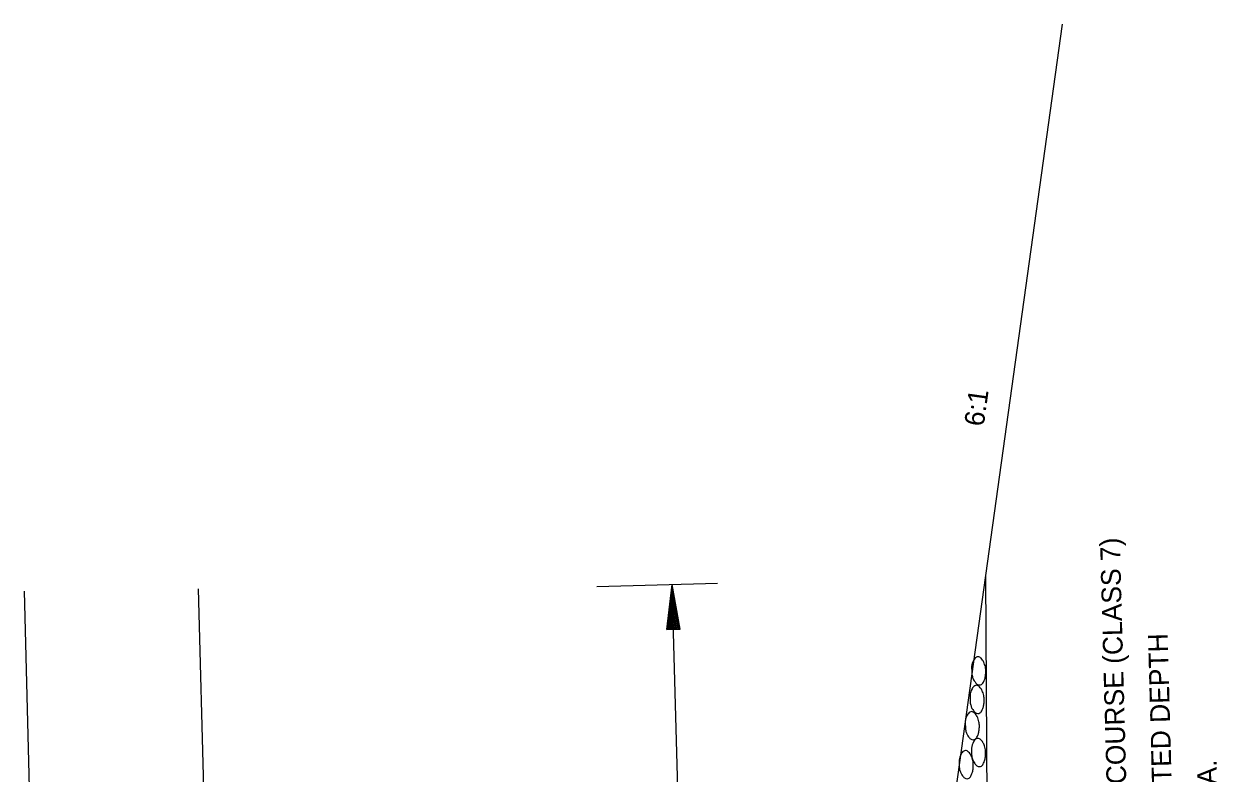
# Model space of a CAD drawing. Extents: x 1926836 to 1933254, y 596317 to 604524.
# Drawn here: x 1932418.2 to 1932782.8, y 597644.8 to 597872.5 of the extents above; entities that cross this region are included whole.
import ezdxf

# ---------------------------------------------------------------- set-up
doc = ezdxf.new("R2010")
doc.units = 0
doc.layers.add('Default', color=7, linetype='Continuous')

msp = doc.modelspace()

# ---------------------------------------------------------------- linework, layer by layer
at = {"layer": 'Default'}
for p, q in [((1932679.06, 597479.65), (1932733.75, 597872.49)), ((1932713.69, 597228.79), (1932710.43, 597704.89)), ((1932471.09, 597701.01), (1932477.06, 597478.58)), ((1932592.27, 597701.72), (1932628.91, 597702.7)), ((1932613.54, 597688.61), (1932615.21, 597702.34)), ((1932621.23, 597478.1), (1932615.21, 597702.34)), ((1932617.64, 597688.72), (1932615.21, 597702.34)), ((1932418.22, 597700.29), (1932424.29, 597474.09)), ((1932613.87, 597688.61), (1932615.27, 597700.05)), ((1932614.23, 597688.62), (1932615.34, 597697.68)), ((1932617.3, 597688.71), (1932615.27, 597700.05)), ((1932616.96, 597688.7), (1932615.34, 597697.68)), ((1932614.56, 597688.63), (1932615.4, 597695.39)), ((1932616.6, 597688.69), (1932615.4, 597695.39)), ((1932614.93, 597688.64), (1932615.46, 597693.08)), ((1932615.26, 597688.65), (1932615.52, 597690.79)), ((1932616.27, 597688.68), (1932615.46, 597693.08)), ((1932615.91, 597688.67), (1932615.52, 597690.79)), ((1932613.54, 597688.61), (1932617.64, 597688.72))]:
    msp.add_line(p, q, dxfattribs=at)
for points in [[(1932706.2, 597675.92), (1932706.17, 597677.44), (1932706.76, 597679.27), (1932707.6, 597680.22), (1932708.1, 597680.37), (1932709.04, 597679.9), (1932709.47, 597679.38), (1932709.98, 597678.42), (1932710.4, 597676.92), (1932710.46, 597676.19), (1932710.42, 597675.05), (1932710.23, 597673.84), (1932709.87, 597672.88), (1932709.19, 597671.97), (1932708.57, 597671.81), (1932707.79, 597672.05), (1932707.2, 597672.72), (1932706.75, 597673.36), (1932706.4, 597674.33), (1932706.24, 597674.96), (1932706.2, 597675.92)], [(1932705.72, 597667.26), (1932705.69, 597668.77), (1932706.28, 597670.61), (1932707.11, 597671.55), (1932707.61, 597671.7), (1932708.55, 597671.23), (1932708.98, 597670.71), (1932709.5, 597669.76), (1932709.91, 597668.25), (1932709.98, 597667.53), (1932709.93, 597666.38), (1932709.74, 597665.17), (1932709.38, 597664.21), (1932708.7, 597663.3), (1932708.09, 597663.14), (1932707.3, 597663.38), (1932706.72, 597664.06), (1932706.27, 597664.7), (1932705.91, 597665.68), (1932705.75, 597666.29), (1932705.72, 597667.26)], [(1932704.25, 597659.28), (1932704.22, 597660.8), (1932704.81, 597662.64), (1932705.64, 597663.58), (1932706.14, 597663.73), (1932707.08, 597663.26), (1932707.52, 597662.74), (1932708.02, 597661.78), (1932708.44, 597660.28), (1932708.51, 597659.55), (1932708.46, 597658.41), (1932708.28, 597657.2), (1932707.91, 597656.24), (1932707.24, 597655.33), (1932706.61, 597655.17), (1932705.83, 597655.41), (1932705.25, 597656.09), (1932704.8, 597656.72), (1932704.44, 597657.69), (1932704.29, 597658.32), (1932704.25, 597659.28)], [(1932706.15, 597651.15), (1932706.12, 597652.66), (1932706.71, 597654.5), (1932707.54, 597655.45), (1932708.04, 597655.6), (1932708.98, 597655.12), (1932709.42, 597654.61), (1932709.93, 597653.65), (1932710.34, 597652.15), (1932710.41, 597651.42), (1932710.36, 597650.28), (1932710.18, 597649.06), (1932709.81, 597648.1), (1932709.14, 597647.2), (1932708.52, 597647.04), (1932707.73, 597647.28), (1932707.15, 597647.95), (1932706.7, 597648.59), (1932706.34, 597649.56), (1932706.18, 597650.19), (1932706.15, 597651.15)], [(1932702.4, 597647.45), (1932702.37, 597648.96), (1932702.96, 597650.8), (1932703.79, 597651.74), (1932704.29, 597651.9), (1932705.23, 597651.42), (1932705.68, 597650.9), (1932706.18, 597649.95), (1932706.59, 597648.45), (1932706.66, 597647.72), (1932706.61, 597646.58), (1932706.42, 597645.36), (1932706.06, 597644.4), (1932705.38, 597643.49), (1932704.77, 597643.34), (1932703.98, 597643.58), (1932703.4, 597644.25), (1932702.95, 597644.89), (1932702.6, 597645.86), (1932702.43, 597646.49), (1932702.4, 597647.45)]]:
    msp.add_spline(points, degree=3, dxfattribs=at)

# ---------------------------------------------------------------- texts
for s, rotation, p in [('6:1', 82.0761, (1932709.8, 597750.11)), ('AGGREGATE BASE COURSE (CLASS 7)', 91.5377, (1932755.23, 597565.09)), ('VARIABLE COMPACTED DEPTH', 91.5377, (1932769.01, 597565.46)), ('57.00 TONS PER STA.', 91.5377, (1932782.8, 597565.83))]:
    msp.add_text(s, height=6, rotation=rotation, dxfattribs=at).set_placement(p)

doc.saveas('drawing.dxf')
